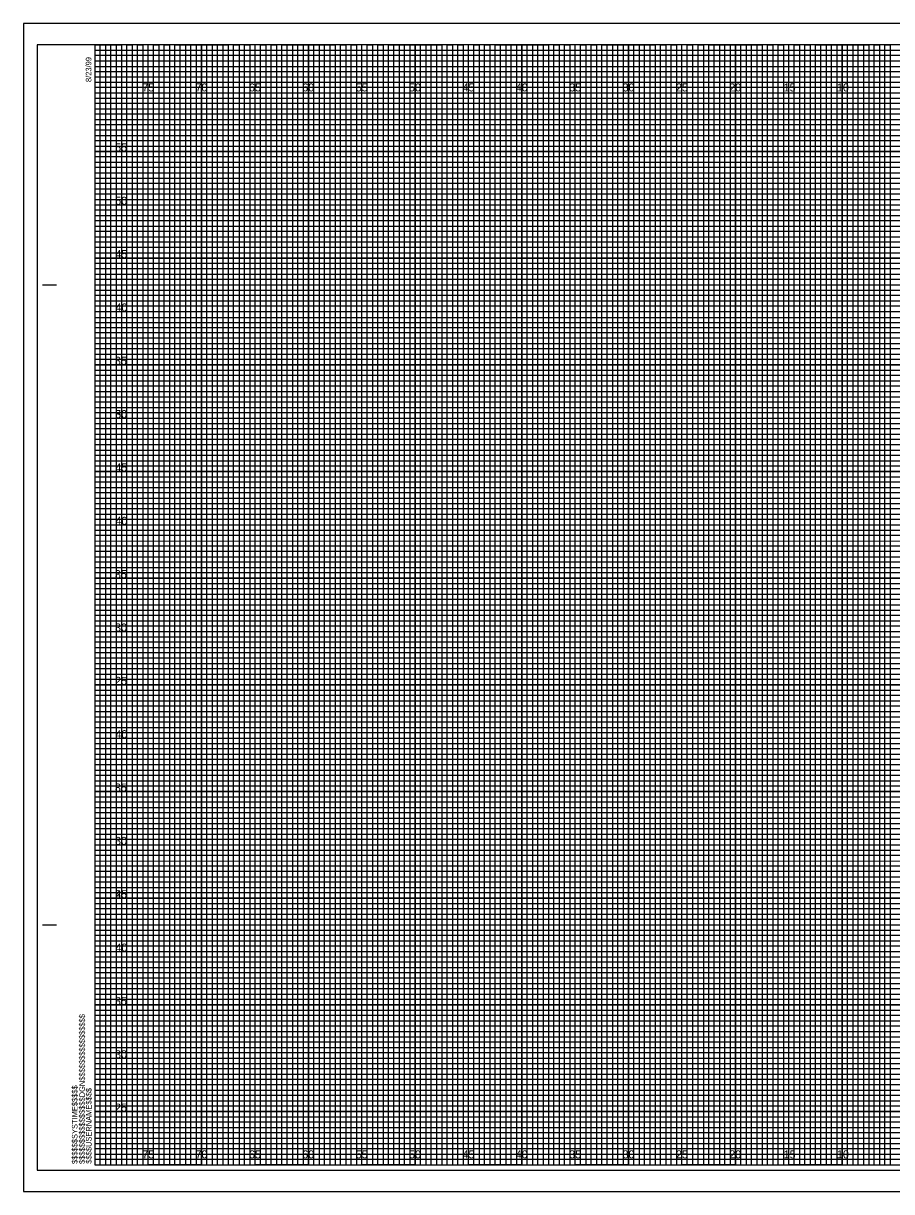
# Model space of a CAD drawing. Extents: x -7 to 162, y 107 to 217.
# Drawn here: x -6.7 to 74.6, y 107.5 to 217 of the extents above; entities that cross this region are included whole.
import ezdxf

# ---------------------------------------------------------------- set-up
doc = ezdxf.new("R2010")
doc.units = 0
for name, color, linetype in [('Exist XS Center Line Elevation Label', 7, 'Continuous'), ('Exist XS Ground Line', 7, 'Continuous'), ('Prop CMT Pvmt Course 1', 7, 'Continuous'), ('Prop CMT Pvmt Course 2', 7, 'Continuous'), ('Prop CMT Pvmt Course 3', 7, 'Continuous'), ('Prop CMT Shld Paved Course 1', 7, 'Continuous'), ('Prop CMT Shld Paved Course 3', 7, 'Continuous'), ('Prop CMT Slope Grass', 7, 'Continuous'), ('Raster_Level_0', 7, 'Continuous'), ('Scratch_Level_0', 7, 'Continuous')]:
    doc.layers.add(name, color=color, linetype=linetype)

msp = doc.modelspace()

# ---------------------------------------------------------------- linework, layer by layer
at = {"layer": 'Exist XS Center Line Elevation Label'}
for points in [[(0, 215), (2.5, 215), (2.5, 110), (7.5, 110), (7.5, 215), (12.5, 215), (12.5, 110), (17.5, 110), (17.5, 215), (22.5, 215), (22.5, 110), (27.5, 110), (27.5, 215), (32.5, 215), (32.5, 110), (37.5, 110), (37.5, 215), (42.5, 215), (42.5, 110), (47.5, 110), (47.5, 215), (52.5, 215), (52.5, 110), (57.5, 110), (57.5, 215), (62.5, 215), (62.5, 110), (67.5, 110), (67.5, 215), (72.5, 215), (72.5, 110), (77.5, 110)], [(0, 212.5), (137.5, 212.5)], [(0, 202.5), (160, 202.5), (160, 207.5), (0, 207.5)], [(0, 192.5), (160, 192.5), (160, 197.5), (0, 197.5)], [(0, 182.5), (160, 182.5), (160, 187.5), (0, 187.5)], [(0, 172.5), (160, 172.5), (160, 177.5), (0, 177.5)], [(0, 162.5), (160, 162.5), (160, 167.5), (0, 167.5)], [(0, 152.5), (160, 152.5), (160, 157.5), (0, 157.5)], [(0, 142.5), (160, 142.5), (160, 147.5), (0, 147.5)], [(0, 132.5), (160, 132.5), (160, 137.5), (0, 137.5)], [(0, 122.5), (160, 122.5), (160, 127.5), (0, 127.5)], [(0, 112.5), (160, 112.5), (160, 117.5), (0, 117.5)]]:
    msp.add_lwpolyline(points, dxfattribs=at)
at = {"layer": 'Exist XS Ground Line'}
for p, q in [((5, 215), (0, 215)), ((5, 110), (5, 215)), ((15, 215), (10, 215)), ((10, 215), (10, 110)), ((15, 110), (15, 215)), ((25, 215), (20, 215)), ((20, 215), (20, 110)), ((25, 110), (25, 215)), ((35, 215), (30, 215)), ((30, 215), (30, 110)), ((35, 110), (35, 215)), ((45, 215), (40, 215)), ((40, 215), (40, 110)), ((45, 110), (45, 215)), ((55, 215), (50, 215)), ((50, 215), (50, 110)), ((55, 110), (55, 215)), ((65, 215), (60, 215)), ((60, 215), (60, 110)), ((65, 110), (65, 215)), ((75, 215), (70, 215)), ((70, 215), (70, 110)), ((10, 110), (5, 110)), ((20, 110), (15, 110)), ((30, 110), (25, 110)), ((40, 110), (35, 110)), ((50, 110), (45, 110)), ((60, 110), (55, 110)), ((70, 110), (65, 110))]:
    msp.add_line(p, q, dxfattribs=at)
for points in [[(0, 210), (160, 210), (160, 205), (0, 205)], [(0, 200), (160, 200), (160, 195), (0, 195)], [(0, 190), (160, 190), (160, 185), (0, 185)], [(0, 180), (160, 180), (160, 175), (0, 175)], [(0, 170), (160, 170), (160, 165), (0, 165)], [(0, 160), (160, 160), (160, 155), (0, 155)], [(0, 150), (160, 150), (160, 145), (0, 145)], [(0, 140), (160, 140), (160, 135), (0, 135)], [(0, 130), (160, 130), (160, 125), (0, 125)], [(0, 120), (160, 120), (160, 115), (0, 115)]]:
    msp.add_lwpolyline(points, dxfattribs=at)
at = {"layer": 'Prop CMT Pvmt Course 1'}
msp.add_lwpolyline([(-5.4, 109.5), (161.2, 109.5), (161.2, 215), (-5.4, 215)], close=True, dxfattribs=at)
at = {"layer": 'Prop CMT Pvmt Course 2'}
for p, q in [((5, 110), (5, 215)), ((10, 110), (10, 215)), ((15, 110), (15, 215)), ((20, 110), (20, 215)), ((25, 110), (25, 215)), ((30, 110), (30, 215)), ((35, 110), (35, 215)), ((40, 110), (40, 215)), ((45, 110), (45, 215)), ((50, 110), (50, 215)), ((55, 110), (55, 215)), ((60, 110), (60, 215)), ((65, 110), (65, 215)), ((70, 110), (70, 215)), ((0, 210), (160, 210)), ((0, 205), (160, 205)), ((0, 200), (160, 200)), ((0, 195), (160, 195)), ((0, 190), (160, 190)), ((0, 185), (160, 185)), ((0, 180), (160, 180)), ((0, 175), (160, 175)), ((0, 170), (160, 170)), ((0, 165), (160, 165)), ((0, 160), (160, 160)), ((0, 155), (160, 155)), ((0, 150), (160, 150)), ((0, 145), (160, 145)), ((0, 140), (160, 140)), ((0, 135), (160, 135)), ((0, 130), (160, 130)), ((0, 125), (160, 125)), ((0, 120), (160, 120)), ((0, 115), (160, 115))]:
    msp.add_line(p, q, dxfattribs=at)
at = {"layer": 'Prop CMT Pvmt Course 3'}
for p, q in [((161.65, 217), (-6.7, 217)), ((-6.7, 217), (-6.7, 107.5)), ((-6.7, 107.5), (161.65, 107.5))]:
    msp.add_line(p, q, dxfattribs=at)
at = {"layer": 'Prop CMT Shld Paved Course 1'}
for points in [[(0, 110), (0.5, 110), (0.5, 215), (1, 215), (1, 110)], [(1, 110), (1.5, 110), (1.5, 215), (2, 215), (2, 110)], [(2.5, 110), (3, 110), (3, 215), (3.5, 215), (3.5, 110)], [(3.5, 110), (4, 110), (4, 215), (4.5, 215), (4.5, 110)], [(5, 110), (5.5, 110), (5.5, 215), (6, 215), (6, 110)], [(6, 110), (6.5, 110), (6.5, 215), (7, 215), (7, 110)], [(7.5, 110), (8, 110), (8, 215), (8.5, 215), (8.5, 110)], [(8.5, 110), (9, 110), (9, 215), (9.5, 215), (9.5, 110)], [(10, 110), (10.5, 110), (10.5, 215), (11, 215), (11, 110)], [(11, 110), (11.5, 110), (11.5, 215), (12, 215), (12, 110)], [(12.5, 110), (13, 110), (13, 215), (13.5, 215), (13.5, 110)], [(13.5, 110), (14, 110), (14, 215), (14.5, 215), (14.5, 110)], [(15, 110), (15.5, 110), (15.5, 215), (16, 215), (16, 110)], [(16, 110), (16.5, 110), (16.5, 215), (17, 215), (17, 110)], [(17.5, 110), (18, 110), (18, 215), (18.5, 215), (18.5, 110)], [(18.5, 110), (19, 110), (19, 215), (19.5, 215), (19.5, 110)], [(20, 110), (20.5, 110), (20.5, 215), (21, 215), (21, 110)], [(21, 110), (21.5, 110), (21.5, 215), (22, 215), (22, 110)], [(22.5, 110), (23, 110), (23, 215), (23.5, 215), (23.5, 110)], [(23.5, 110), (24, 110), (24, 215), (24.5, 215), (24.5, 110)], [(25, 110), (25.5, 110), (25.5, 215), (26, 215), (26, 110)], [(26, 110), (26.5, 110), (26.5, 215), (27, 215), (27, 110)], [(27.5, 110), (28, 110), (28, 215), (28.5, 215), (28.5, 110)], [(28.5, 110), (29, 110), (29, 215), (29.5, 215), (29.5, 110)], [(30, 110), (30.5, 110), (30.5, 215), (31, 215), (31, 110)], [(31, 110), (31.5, 110), (31.5, 215), (32, 215), (32, 110)], [(32.5, 110), (33, 110), (33, 215), (33.5, 215), (33.5, 110)], [(33.5, 110), (34, 110), (34, 215), (34.5, 215), (34.5, 110)], [(35, 110), (35.5, 110), (35.5, 215), (36, 215), (36, 110)], [(36, 110), (36.5, 110), (36.5, 215), (37, 215), (37, 110)], [(37.5, 110), (38, 110), (38, 215), (38.5, 215), (38.5, 110)], [(38.5, 110), (39, 110), (39, 215), (39.5, 215), (39.5, 110)], [(40, 110), (40.5, 110), (40.5, 215), (41, 215), (41, 110)], [(41, 110), (41.5, 110), (41.5, 215), (42, 215), (42, 110)], [(42.5, 110), (43, 110), (43, 215), (43.5, 215), (43.5, 110)], [(43.5, 110), (44, 110), (44, 215), (44.5, 215), (44.5, 110)], [(45, 110), (45.5, 110), (45.5, 215), (46, 215), (46, 110)], [(46, 110), (46.5, 110), (46.5, 215), (47, 215), (47, 110)], [(47.5, 110), (48, 110), (48, 215), (48.5, 215), (48.5, 110)], [(48.5, 110), (49, 110), (49, 215), (49.5, 215), (49.5, 110)], [(50, 110), (50.5, 110), (50.5, 215), (51, 215), (51, 110)], [(51, 110), (51.5, 110), (51.5, 215), (52, 215), (52, 110)], [(52.5, 110), (53, 110), (53, 215), (53.5, 215), (53.5, 110)], [(53.5, 110), (54, 110), (54, 215), (54.5, 215), (54.5, 110)], [(55, 110), (55.5, 110), (55.5, 215), (56, 215), (56, 110)], [(56, 110), (56.5, 110), (56.5, 215), (57, 215), (57, 110)], [(57.5, 110), (58, 110), (58, 215), (58.5, 215), (58.5, 110)], [(58.5, 110), (59, 110), (59, 215), (59.5, 215), (59.5, 110)], [(60, 110), (60.5, 110), (60.5, 215), (61, 215), (61, 110)], [(61, 110), (61.5, 110), (61.5, 215), (62, 215), (62, 110)], [(62.5, 110), (63, 110), (63, 215), (63.5, 215), (63.5, 110)], [(63.5, 110), (64, 110), (64, 215), (64.5, 215), (64.5, 110)], [(65, 110), (65.5, 110), (65.5, 215), (66, 215), (66, 110)], [(66, 110), (66.5, 110), (66.5, 215), (67, 215), (67, 110)], [(67.5, 110), (68, 110), (68, 215), (68.5, 215), (68.5, 110)], [(68.5, 110), (69, 110), (69, 215), (69.5, 215), (69.5, 110)], [(70, 110), (70.5, 110), (70.5, 215), (71, 215), (71, 110)], [(71, 110), (71.5, 110), (71.5, 215), (72, 215), (72, 110)], [(72.5, 110), (73, 110), (73, 215), (73.5, 215), (73.5, 110)], [(73.5, 110), (74, 110), (74, 215), (74.5, 215), (74.5, 110)]]:
    msp.add_lwpolyline(points, dxfattribs=at)
at = {"layer": 'Prop CMT Shld Paved Course 3'}
msp.add_lwpolyline([(-6.7, 107.5), (161.65, 107.5), (161.65, 217), (-6.7, 217)], close=True, dxfattribs=at)
at = {"layer": 'Prop CMT Slope Grass'}
for p, q in [((-4.9, 192.5), (-3.65, 192.5)), ((-4.85, 192.5), (-3.6, 192.5)), ((-4.9, 132.5), (-3.65, 132.5)), ((-4.85, 132.5), (-3.6, 132.5)), ((0, 110), (0, 110)), ((0, 110), (0, 110)), ((0, 110), (0, 110)), ((0, 110), (0, 110)), ((0, 110), (0, 110)), ((0, 110), (0, 110)), ((0, 110), (0, 110))]:
    msp.add_line(p, q, dxfattribs=at)
msp.add_lwpolyline([(160, 215), (0, 215), (0, 110), (160, 110)], close=True, dxfattribs=at)
at = {"layer": 'Scratch_Level_0'}
for p, q in [((0, 214.5), (130, 214.5)), ((130, 213.99), (0, 213.99)), ((0, 213.99), (0, 213.5)), ((0, 213.5), (130, 213.5)), ((130, 212.94), (0, 212.94)), ((0, 212.94), (0, 212)), ((0, 212), (160, 212))]:
    msp.add_line(p, q, dxfattribs=at)
for points in [[(0, 211.5), (135, 211.5), (160, 211.5), (160, 211), (0, 211)], [(0, 210.5), (160, 210.5), (160, 209.5), (0, 209.5)], [(0, 209), (160, 209), (160, 208.5), (0, 208.49)], [(0, 208), (160, 208), (160, 207), (0, 207)], [(0, 206.5), (160, 206.5), (160, 206), (0, 206)], [(0, 205.5), (160, 205.5), (160, 204.5), (0, 204.5)], [(0, 204), (160, 204), (160, 203.5), (0, 203.5)], [(0, 203), (160, 203), (160, 202), (0, 202)], [(0, 201.5), (160, 201.5), (160, 201), (0, 201)], [(0, 200.5), (160, 200.5), (160, 199.5), (0, 199.5)], [(0, 199), (160, 199), (160, 198.5), (0, 198.5)], [(0, 198), (160, 198), (160, 196.97), (160, 196.5), (160, 196), (0, 196)], [(0, 197), (160, 197), (160, 196.5), (0, 196.5)], [(0, 195.5), (160, 195.5), (160, 194.5), (0, 194.52)], [(0, 194.52), (160, 194.5), (160, 194), (0, 194)], [(0, 193.5), (160, 193.5), (160, 193), (0, 193)], [(0, 192), (160, 192), (160, 191.5), (0, 191.5)], [(0, 191), (160, 191), (160, 190.5), (0, 190.5)], [(-0.04, 189.44), (160, 189.44), (160, 188.94), (-0.04, 188.94)], [(0, 188.5), (160, 188.5), (160, 188), (0, 188)], [(0, 187), (160, 187), (160, 186.5), (0, 186.5)], [(0, 186), (160, 186), (160, 185.5), (0, 185.5)], [(0, 184.5), (160, 184.5), (160, 184), (0, 184)], [(0, 183.5), (160, 183.5), (160, 183), (0, 183)], [(0, 182), (160, 182), (160, 181.5), (0, 181.5)], [(0, 181), (160, 181), (160, 180.5), (0, 180.5)], [(0, 179.5), (160, 179.5), (160, 178.99), (0, 179)], [(0, 178.5), (160, 178.5), (160, 178), (0, 178)], [(0, 177), (160, 177), (160, 176.5), (0, 176.5)], [(0, 176), (160, 176), (160, 175.5), (0, 175.5)], [(0, 174.5), (160, 174.5), (160, 174), (0, 174)], [(0, 173.5), (160, 173.5), (160, 173), (0, 173)], [(0, 172), (160, 172), (160, 171.5), (0, 171.5)], [(0, 171), (160, 171), (160, 170.5), (0, 170.5)], [(0, 169.5), (160, 169.5), (160, 169), (0, 169)], [(0, 168.5), (160.03, 168.46), (160, 168), (0, 168)], [(0, 167), (160, 167), (160, 166.5), (0, 166.5)], [(0, 166), (160, 166), (160, 165.5), (0, 165.5)], [(0, 164.5), (160, 164.5), (160, 164), (0, 164)], [(0, 163.5), (160, 163.5), (160, 163), (0, 163)], [(0, 162), (160, 162), (160, 161.5), (0, 161.5)], [(0, 161), (160, 161), (160, 160.5), (0, 160.5)], [(0, 159.5), (160, 159.5), (160, 159), (0, 159)], [(0, 158.5), (160, 158.5), (160, 158), (0, 158)], [(0, 157), (160, 157), (160, 156.5), (0, 156.5)], [(0, 156), (160, 156), (160, 155.5), (0, 155.5)], [(0, 154.5), (160, 154.5), (160, 154), (0, 154)], [(0, 153.5), (160, 153.5), (160, 153), (0, 153)], [(0, 152), (160, 152), (160, 151.5), (0, 151.5)], [(0, 151), (160, 151), (160, 150.5), (0, 150.5)], [(0, 149.5), (160, 149.5), (160, 148.99), (0, 149)], [(0, 148.5), (160, 148.5), (160, 148), (0, 148)], [(0, 147), (160, 147), (160, 146.5), (0, 146.5)], [(0, 146), (160, 146), (160, 145.5), (0, 145.5)], [(0, 144.5), (160, 144.5), (160, 144), (0, 144)], [(0, 143.5), (160, 143.5), (160, 143), (0, 143)], [(0, 142), (160, 142), (160, 141.5), (0, 141.5)], [(0, 141), (160, 141), (160, 140.5), (0, 140.5)], [(0, 139.5), (160, 139.5), (160, 139), (0, 139)], [(0, 138.5), (160.03, 138.46), (160, 138), (0, 138)], [(0, 137), (160, 137), (160, 136.5), (0, 136.5)], [(0, 136), (160, 136), (160, 135.5), (0, 135.5)], [(0, 134.5), (160, 134.5), (160, 134), (0, 134)], [(0, 133.5), (160, 133.5), (160, 133), (0, 133)], [(0, 132), (160, 132), (160, 131.5), (0, 131.5)], [(0, 131), (160, 131), (160, 130.5), (0, 130.5)], [(0, 129.5), (160, 129.5), (160, 129), (0, 129)], [(0, 128.5), (160, 128.5), (160, 128), (0, 128)], [(0, 127), (160, 127), (160, 126.5), (0, 126.5)], [(0, 126), (160, 126), (160, 125.5), (0, 125.5)], [(0, 124.5), (160, 124.5), (160, 124), (0, 124)], [(0, 123.5), (160, 123.5), (160, 123), (0, 123)], [(0, 122), (160, 122), (160, 121.5), (0, 121.5)], [(0, 121), (160, 121), (160, 120.5), (0, 120.5)], [(0, 119.5), (160, 119.5), (160, 119), (0, 119)], [(0, 118.5), (160, 118.5), (160, 118), (0, 118)], [(0, 117), (160, 117), (160, 116.5), (0, 116.5)], [(0, 116), (160, 116), (160, 115.5), (0, 115.5)], [(0, 114.5), (160, 114.5), (160, 114), (0, 114)], [(0, 113.5), (160, 113.5), (160, 113), (0, 113)], [(0, 112), (160, 112), (160, 111.5), (0, 111.5)], [(0, 111), (160, 111), (160, 110.5), (0, 110.5)]]:
    msp.add_lwpolyline(points, dxfattribs=at)

# ---------------------------------------------------------------- texts
at = {"layer": 'Prop CMT Pvmt Course 3'}
for s, p in [('55', (1.9, 205)), ('50', (1.91, 200)), ('45', (1.92, 195)), ('40', (1.93, 190)), ('35', (1.88, 185)), ('30', (1.89, 180)), ('50', (1.91, 180)), ('45', (1.92, 175)), ('40', (1.93, 170)), ('35', (1.88, 165)), ('30', (1.89, 160)), ('25', (1.89, 155)), ('40', (1.93, 150)), ('35', (1.88, 145)), ('30', (1.89, 140)), ('25', (1.89, 135)), ('45', (1.92, 135)), ('40', (1.93, 130)), ('35', (1.88, 125)), ('30', (1.89, 120)), ('25', (1.89, 115))]:
    msp.add_text(s, height=0.75, dxfattribs=at).set_placement(p)
at = {"layer": 'Prop CMT Slope Grass'}
for s, p in [('8/23/99', (-0.33, 211.5)), ('$$$$$$$$$$$$$$$$DGN$$$$$$$$$$$$$$$$', (-0.94, 110.09)), ('$$$$$$SYSTIME$$$$$', (-1.63, 110.09)), ('$$$$USERNAME$$$$', (-0.31, 110.12))]:
    msp.add_text(s, height=0.525, rotation=90, dxfattribs=at).set_placement(p)
at = {"layer": 'Raster_Level_0'}
for s, p in [('75', (4.44, 210.62)), ('70', (9.43, 210.62)), ('65', (14.44, 210.62)), ('60', (19.43, 210.62)), ('55', (24.44, 210.62)), ('50', (29.43, 210.62)), ('45', (34.44, 210.62)), ('40', (39.43, 210.62)), ('35', (44.44, 210.62)), ('30', (49.43, 210.62)), ('25', (54.44, 210.62)), ('20', (59.43, 210.62)), ('15', (64.53, 210.62)), ('10', (69.52, 210.62)), ('75', (4.44, 110.62)), ('70', (9.43, 110.62)), ('65', (14.44, 110.62)), ('60', (19.43, 110.62)), ('55', (24.44, 110.62)), ('50', (29.43, 110.62)), ('45', (34.44, 110.62)), ('40', (39.43, 110.62)), ('35', (44.44, 110.62)), ('30', (49.43, 110.62)), ('25', (54.44, 110.62)), ('20', (59.43, 110.62)), ('15', (64.53, 110.62)), ('10', (69.52, 110.62))]:
    msp.add_text(s, height=0.75, dxfattribs=at).set_placement(p)

doc.saveas('drawing.dxf')
